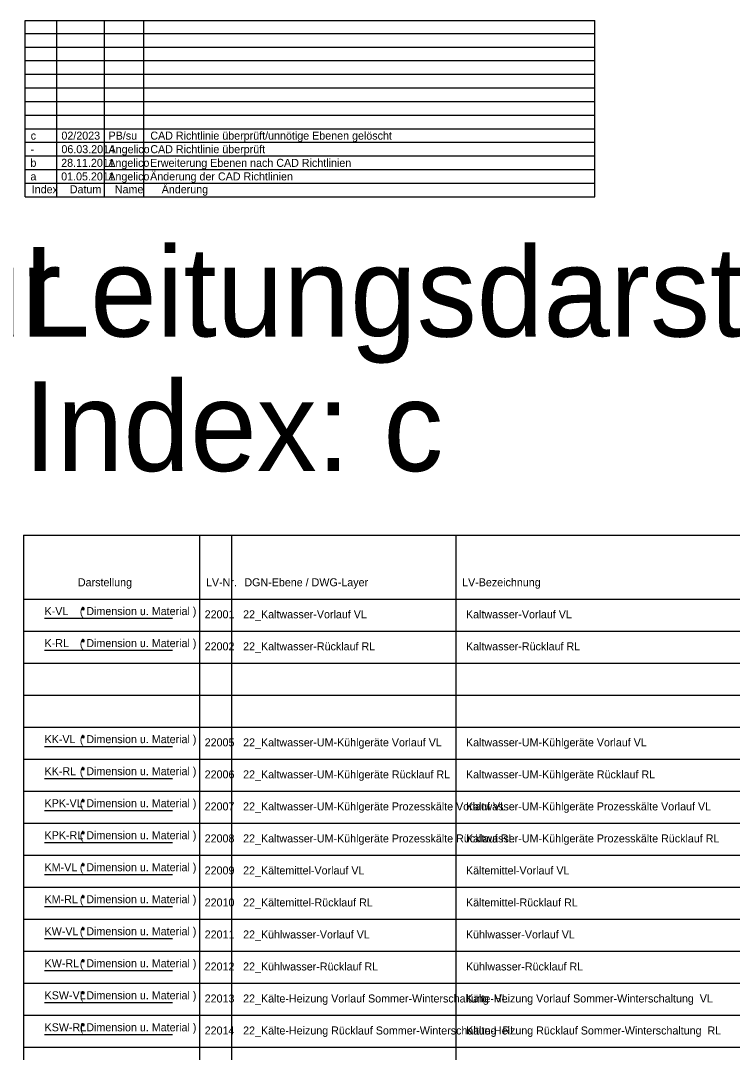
# Model space of a CAD drawing. Extents: x -14.3 to 23.8, y -56.3 to 8.
# Drawn here: x -0.04 to 11.07, y -8.08 to 8.03 of the extents above; entities that cross this region are included whole.
import ezdxf

# ---------------------------------------------------------------- set-up
doc = ezdxf.new("R2010")
doc.units = 0
for name, color, linetype in [('22_Kaltwasser-Rücklauf RL', 7, 'Continuous'), ('22_Kaltwasser-UM-Kühlgeräte Prozesskälte Rücklauf RL', 7, 'Continuous'), ('22_Kaltwasser-UM-Kühlgeräte Prozesskälte Vorlauf VL', 7, 'Continuous'), ('22_Kaltwasser-UM-Kühlgeräte Rücklauf RL', 7, 'Continuous'), ('22_Kaltwasser-UM-Kühlgeräte Vorlauf VL', 7, 'Continuous'), ('22_Kaltwasser-Vorlauf VL', 7, 'Continuous'), ('22_Kälte-Heizung Rücklauf Sommer-Winterschaltung  RL', 7, 'Continuous'), ('22_Kälte-Heizung Vorlauf Sommer-Winterschaltung  VL', 7, 'Continuous'), ('22_Kältemittel-Rücklauf RL', 7, 'Continuous'), ('22_Kältemittel-Vorlauf VL', 7, 'Continuous'), ('22_Kühlwasser-Rücklauf RL', 7, 'Continuous'), ('22_Kühlwasser-Vorlauf VL', 7, 'Continuous'), ('Default', 7, 'Continuous')]:
    doc.layers.add(name, color=color, linetype=linetype)

msp = doc.modelspace()

# ---------------------------------------------------------------- linework, layer by layer
at = {"layer": '22_Kaltwasser-Rücklauf RL'}
for p, q in [((0.908, -1.65), (0.952, -1.65)), ((0.914, -1.634), (0.946, -1.666)), ((0.946, -1.634), (0.914, -1.666)), ((0.93, -1.628), (0.93, -1.672)), ((0.33, -1.8), (2.33, -1.8))]:
    msp.add_line(p, q, dxfattribs=at)
at = {"layer": '22_Kaltwasser-UM-Kühlgeräte Prozesskälte Rücklauf RL'}
for p, q in [((0.908, -4.65), (0.952, -4.65)), ((0.914, -4.634), (0.946, -4.666)), ((0.946, -4.634), (0.914, -4.666)), ((0.93, -4.628), (0.93, -4.672)), ((0.33, -4.8), (2.33, -4.8))]:
    msp.add_line(p, q, dxfattribs=at)
at = {"layer": '22_Kaltwasser-UM-Kühlgeräte Prozesskälte Vorlauf VL'}
for p, q in [((0.908, -4.15), (0.952, -4.15)), ((0.914, -4.134), (0.946, -4.166)), ((0.946, -4.134), (0.914, -4.166)), ((0.93, -4.128), (0.93, -4.172)), ((0.33, -4.3), (2.33, -4.3))]:
    msp.add_line(p, q, dxfattribs=at)
at = {"layer": '22_Kaltwasser-UM-Kühlgeräte Rücklauf RL'}
for p, q in [((0.908, -3.65), (0.952, -3.65)), ((0.914, -3.634), (0.946, -3.666)), ((0.946, -3.634), (0.914, -3.666)), ((0.93, -3.628), (0.93, -3.672)), ((0.33, -3.8), (2.33, -3.8))]:
    msp.add_line(p, q, dxfattribs=at)
at = {"layer": '22_Kaltwasser-UM-Kühlgeräte Vorlauf VL'}
for p, q in [((0.908, -3.15), (0.952, -3.15)), ((0.914, -3.134), (0.946, -3.166)), ((0.946, -3.134), (0.914, -3.166)), ((0.93, -3.128), (0.93, -3.172)), ((0.33, -3.3), (2.33, -3.3))]:
    msp.add_line(p, q, dxfattribs=at)
at = {"layer": '22_Kaltwasser-Vorlauf VL'}
for p, q in [((0.93, -1.128), (0.93, -1.172)), ((0.93, -1.128), (0.93, -1.172)), ((0.908, -1.15), (0.952, -1.15)), ((0.908, -1.15), (0.952, -1.15)), ((0.914, -1.134), (0.946, -1.166)), ((0.946, -1.134), (0.914, -1.166)), ((0.914, -1.134), (0.946, -1.166)), ((0.946, -1.134), (0.914, -1.166)), ((0.33, -1.3), (2.33, -1.3))]:
    msp.add_line(p, q, dxfattribs=at)
at = {"layer": '22_Kälte-Heizung Rücklauf Sommer-Winterschaltung  RL'}
for p, q in [((0.908, -7.65), (0.952, -7.65)), ((0.914, -7.634), (0.946, -7.666)), ((0.946, -7.634), (0.914, -7.666)), ((0.93, -7.628), (0.93, -7.672)), ((0.33, -7.8), (2.33, -7.8))]:
    msp.add_line(p, q, dxfattribs=at)
at = {"layer": '22_Kälte-Heizung Vorlauf Sommer-Winterschaltung  VL'}
for p, q in [((0.908, -7.15), (0.952, -7.15)), ((0.914, -7.134), (0.946, -7.166)), ((0.946, -7.134), (0.914, -7.166)), ((0.93, -7.128), (0.93, -7.172)), ((0.33, -7.3), (2.33, -7.3))]:
    msp.add_line(p, q, dxfattribs=at)
at = {"layer": '22_Kältemittel-Rücklauf RL'}
for p, q in [((0.914, -5.634), (0.946, -5.666)), ((0.946, -5.634), (0.914, -5.666)), ((0.93, -5.628), (0.93, -5.672)), ((0.33, -5.8), (2.33, -5.8)), ((0.908, -5.65), (0.952, -5.65))]:
    msp.add_line(p, q, dxfattribs=at)
at = {"layer": '22_Kältemittel-Vorlauf VL'}
for p, q in [((0.908, -5.15), (0.952, -5.15)), ((0.914, -5.134), (0.946, -5.166)), ((0.946, -5.134), (0.914, -5.166)), ((0.93, -5.128), (0.93, -5.172)), ((0.33, -5.3), (2.33, -5.3))]:
    msp.add_line(p, q, dxfattribs=at)
at = {"layer": '22_Kühlwasser-Rücklauf RL'}
for p, q in [((0.908, -6.65), (0.952, -6.65)), ((0.914, -6.634), (0.946, -6.666)), ((0.946, -6.634), (0.914, -6.666)), ((0.93, -6.628), (0.93, -6.672)), ((0.33, -6.8), (2.33, -6.8))]:
    msp.add_line(p, q, dxfattribs=at)
at = {"layer": '22_Kühlwasser-Vorlauf VL'}
for p, q in [((0.908, -6.15), (0.952, -6.15)), ((0.914, -6.134), (0.946, -6.166)), ((0.946, -6.134), (0.914, -6.166)), ((0.93, -6.128), (0.93, -6.172)), ((0.33, -6.3), (2.33, -6.3))]:
    msp.add_line(p, q, dxfattribs=at)
at = {"layer": 'Default'}
for p, q in [((0.029, 5.285), (0.029, 8.034)), ((0.029, 8.034), (8.923, 8.034)), ((0.523, 5.285), (0.523, 8.034)), ((1.264, 5.285), (1.264, 8.034)), ((1.882, 5.285), (1.882, 8.034)), ((8.923, 5.285), (8.923, 8.034)), ((0.029, 7.835), (8.923, 7.835)), ((0.029, 7.622), (8.923, 7.622)), ((0.029, 7.41), (8.923, 7.41)), ((0.029, 7.197), (8.923, 7.197)), ((0.029, 6.985), (8.923, 6.985)), ((0.029, 6.772), (8.923, 6.772)), ((0.029, 6.56), (8.923, 6.56)), ((0.029, 6.347), (8.923, 6.347)), ((0.029, 6.135), (8.923, 6.135)), ((0.029, 5.922), (8.923, 5.922)), ((0.029, 5.71), (8.923, 5.71)), ((0.029, 5.497), (8.923, 5.497)), ((0.029, 5.285), (8.923, 5.285)), ((0.029, 5.285), (8.923, 5.285)), ((0, 0), (0, -53.5)), ((0, 0), (16, 0)), ((2.75, 0), (2.75, -53.5)), ((3.25, 0), (3.25, -53.5)), ((6.75, 0), (6.75, -53.5)), ((0, -1), (14.169, -1)), ((0, -1), (16, -1)), ((0, -1.5), (16, -1.5)), ((0, -2), (16, -2)), ((0, -2.5), (16, -2.5)), ((0, -3), (16, -3)), ((0, -3.5), (16, -3.5)), ((0, -4), (16, -4)), ((0, -4.5), (16, -4.5)), ((0, -5), (16, -5)), ((0, -5.5), (16, -5.5)), ((0, -6), (16, -6)), ((0, -6.5), (16, -6.5)), ((0, -7), (16, -7)), ((0, -7.5), (16, -7.5)), ((0, -8), (16, -8))]:
    msp.add_line(p, q, dxfattribs=at)

# ---------------------------------------------------------------- texts
at = {"layer": '22_Kaltwasser-Rücklauf RL'}
for s, p in [('K-RL', (0.33, -1.75)), ('( Dimension u. Material )', (0.88, -1.75))]:
    msp.add_text(s, height=0.125, dxfattribs=at).set_placement(p)
at = {"layer": '22_Kaltwasser-UM-Kühlgeräte Prozesskälte Rücklauf RL'}
for s, p in [('KPK-RL', (0.33, -4.75)), ('( Dimension u. Material )', (0.88, -4.75))]:
    msp.add_text(s, height=0.125, dxfattribs=at).set_placement(p)
at = {"layer": '22_Kaltwasser-UM-Kühlgeräte Prozesskälte Vorlauf VL'}
for s, p in [('KPK-VL', (0.33, -4.25)), ('( Dimension u. Material )', (0.88, -4.25))]:
    msp.add_text(s, height=0.125, dxfattribs=at).set_placement(p)
at = {"layer": '22_Kaltwasser-UM-Kühlgeräte Rücklauf RL'}
for s, p in [('KK-RL', (0.33, -3.75)), ('( Dimension u. Material )', (0.88, -3.75))]:
    msp.add_text(s, height=0.125, dxfattribs=at).set_placement(p)
at = {"layer": '22_Kaltwasser-UM-Kühlgeräte Vorlauf VL'}
for s, p in [('KK-VL', (0.33, -3.25)), ('( Dimension u. Material )', (0.88, -3.25))]:
    msp.add_text(s, height=0.125, dxfattribs=at).set_placement(p)
at = {"layer": '22_Kaltwasser-Vorlauf VL'}
for s, p in [('K-VL', (0.33, -1.25)), ('( Dimension u. Material )', (0.88, -1.25))]:
    msp.add_text(s, height=0.125, dxfattribs=at).set_placement(p)
at = {"layer": '22_Kälte-Heizung Rücklauf Sommer-Winterschaltung  RL'}
for s, p in [('KSW-RL', (0.33, -7.75)), ('( Dimension u. Material )', (0.88, -7.75))]:
    msp.add_text(s, height=0.125, dxfattribs=at).set_placement(p)
at = {"layer": '22_Kälte-Heizung Vorlauf Sommer-Winterschaltung  VL'}
for s, p in [('KSW-VL', (0.33, -7.25)), ('( Dimension u. Material )', (0.88, -7.25))]:
    msp.add_text(s, height=0.125, dxfattribs=at).set_placement(p)
at = {"layer": '22_Kältemittel-Rücklauf RL'}
for s, p in [('KM-RL', (0.33, -5.75)), ('( Dimension u. Material )', (0.88, -5.75))]:
    msp.add_text(s, height=0.125, dxfattribs=at).set_placement(p)
at = {"layer": '22_Kältemittel-Vorlauf VL'}
for s, p in [('KM-VL', (0.33, -5.25)), ('( Dimension u. Material )', (0.88, -5.25))]:
    msp.add_text(s, height=0.125, dxfattribs=at).set_placement(p)
at = {"layer": '22_Kühlwasser-Rücklauf RL'}
for s, p in [('KW-RL', (0.33, -6.75)), ('( Dimension u. Material )', (0.88, -6.75))]:
    msp.add_text(s, height=0.125, dxfattribs=at).set_placement(p)
at = {"layer": '22_Kühlwasser-Vorlauf VL'}
for s, p in [('( Dimension u. Material )', (0.88, -6.25)), ('KW-VL', (0.33, -6.25))]:
    msp.add_text(s, height=0.125, dxfattribs=at).set_placement(p)
at = {"layer": 'Default'}
for s, height, p in [('02/2023   ', 0.125, (0.593, 6.176)), ('PB/su   ', 0.125, (1.329, 6.176)), ('CAD Richtlinie überprüft/unnötige Ebenen gelöscht                                               ', 0.125, (1.981, 6.176)), ('c     ', 0.125, (0.113, 6.176)), ('-     ', 0.125, (0.113, 5.964)), ('06.03.2014', 0.125, (0.593, 5.964)), ('Angelico', 0.125, (1.329, 5.964)), ('CAD Richtlinie überprüft                                                                        ', 0.125, (1.981, 5.964)), ('b     ', 0.125, (0.109, 5.751)), ('28.11.2011', 0.125, (0.589, 5.751)), ('Angelico', 0.125, (1.325, 5.751)), ('Erweiterung Ebenen nach CAD Richtlinien                                                         ', 0.125, (1.978, 5.751)), ('01.05.2011', 0.125, (0.589, 5.539)), ('Angelico', 0.125, (1.325, 5.539)), ('Änderung der CAD Richtlinien                                                                    ', 0.125, (1.978, 5.539)), ('a     ', 0.125, (0.109, 5.539)), ('Änderung', 0.125, (2.159, 5.338)), ('Index', 0.125, (0.13, 5.338)), ('Datum', 0.125, (0.724, 5.338)), ('Name', 0.125, (1.427, 5.338)), ('Musterlegende für ', 1.4, (-14.5, 3.1)), ('Leitungsdarstellung: Kälte ', 1.4, (0, 3.1)), ('Index: c', 1.4, (0, 1)), ('Darstellung', 0.125, (0.85, -0.8)), ('LV-Nr.', 0.125, (2.85, -0.8)), ('DGN-Ebene / DWG-Layer', 0.125, (3.45, -0.8)), ('LV-Bezeichnung', 0.125, (6.85, -0.8)), ('22001', 0.125, (2.83, -1.3)), ('22_Kaltwasser-Vorlauf VL', 0.125, (3.43, -1.3)), ('Kaltwasser-Vorlauf VL', 0.125, (6.91, -1.3)), ('22002', 0.125, (2.83, -1.8)), ('22_Kaltwasser-Rücklauf RL', 0.125, (3.43, -1.8)), ('Kaltwasser-Rücklauf RL', 0.125, (6.91, -1.8)), ('22005', 0.125, (2.83, -3.3)), ('22_Kaltwasser-UM-Kühlgeräte Vorlauf VL', 0.125, (3.43, -3.3)), ('Kaltwasser-UM-Kühlgeräte Vorlauf VL', 0.125, (6.91, -3.3)), ('22006', 0.125, (2.83, -3.8)), ('22_Kaltwasser-UM-Kühlgeräte Rücklauf RL', 0.125, (3.43, -3.8)), ('Kaltwasser-UM-Kühlgeräte Rücklauf RL', 0.125, (6.91, -3.8)), ('22007', 0.125, (2.83, -4.3)), ('22_Kaltwasser-UM-Kühlgeräte Prozesskälte Vorlauf VL', 0.125, (3.43, -4.3)), ('Kaltwasser-UM-Kühlgeräte Prozesskälte Vorlauf VL', 0.125, (6.91, -4.3)), ('22_Kaltwasser-UM-Kühlgeräte Prozesskälte Rücklauf RL', 0.125, (3.43, -4.8)), ('Kaltwasser-UM-Kühlgeräte Prozesskälte Rücklauf RL', 0.125, (6.91, -4.8)), ('22008', 0.125, (2.83, -4.8)), ('22009', 0.125, (2.83, -5.3)), ('22_Kältemittel-Vorlauf VL', 0.125, (3.43, -5.3)), ('Kältemittel-Vorlauf VL', 0.125, (6.91, -5.3)), ('22010', 0.125, (2.83, -5.8)), ('22_Kältemittel-Rücklauf RL', 0.125, (3.43, -5.8)), ('Kältemittel-Rücklauf RL', 0.125, (6.91, -5.8)), ('22011', 0.125, (2.83, -6.3)), ('22_Kühlwasser-Vorlauf VL', 0.125, (3.43, -6.3)), ('Kühlwasser-Vorlauf VL', 0.125, (6.91, -6.3)), ('22012', 0.125, (2.83, -6.8)), ('22_Kühlwasser-Rücklauf RL', 0.125, (3.43, -6.8)), ('Kühlwasser-Rücklauf RL', 0.125, (6.91, -6.8)), ('22013', 0.125, (2.83, -7.3)), ('22_Kälte-Heizung Vorlauf Sommer-Winterschaltung  VL', 0.125, (3.43, -7.3)), ('Kälte-Heizung Vorlauf Sommer-Winterschaltung  VL', 0.125, (6.91, -7.3)), ('22014', 0.125, (2.83, -7.8)), ('22_Kälte-Heizung Rücklauf Sommer-Winterschaltung  RL', 0.125, (3.43, -7.8)), ('Kälte-Heizung Rücklauf Sommer-Winterschaltung  RL', 0.125, (6.91, -7.8))]:
    msp.add_text(s, height=height, dxfattribs=at).set_placement(p)

doc.saveas('drawing.dxf')
